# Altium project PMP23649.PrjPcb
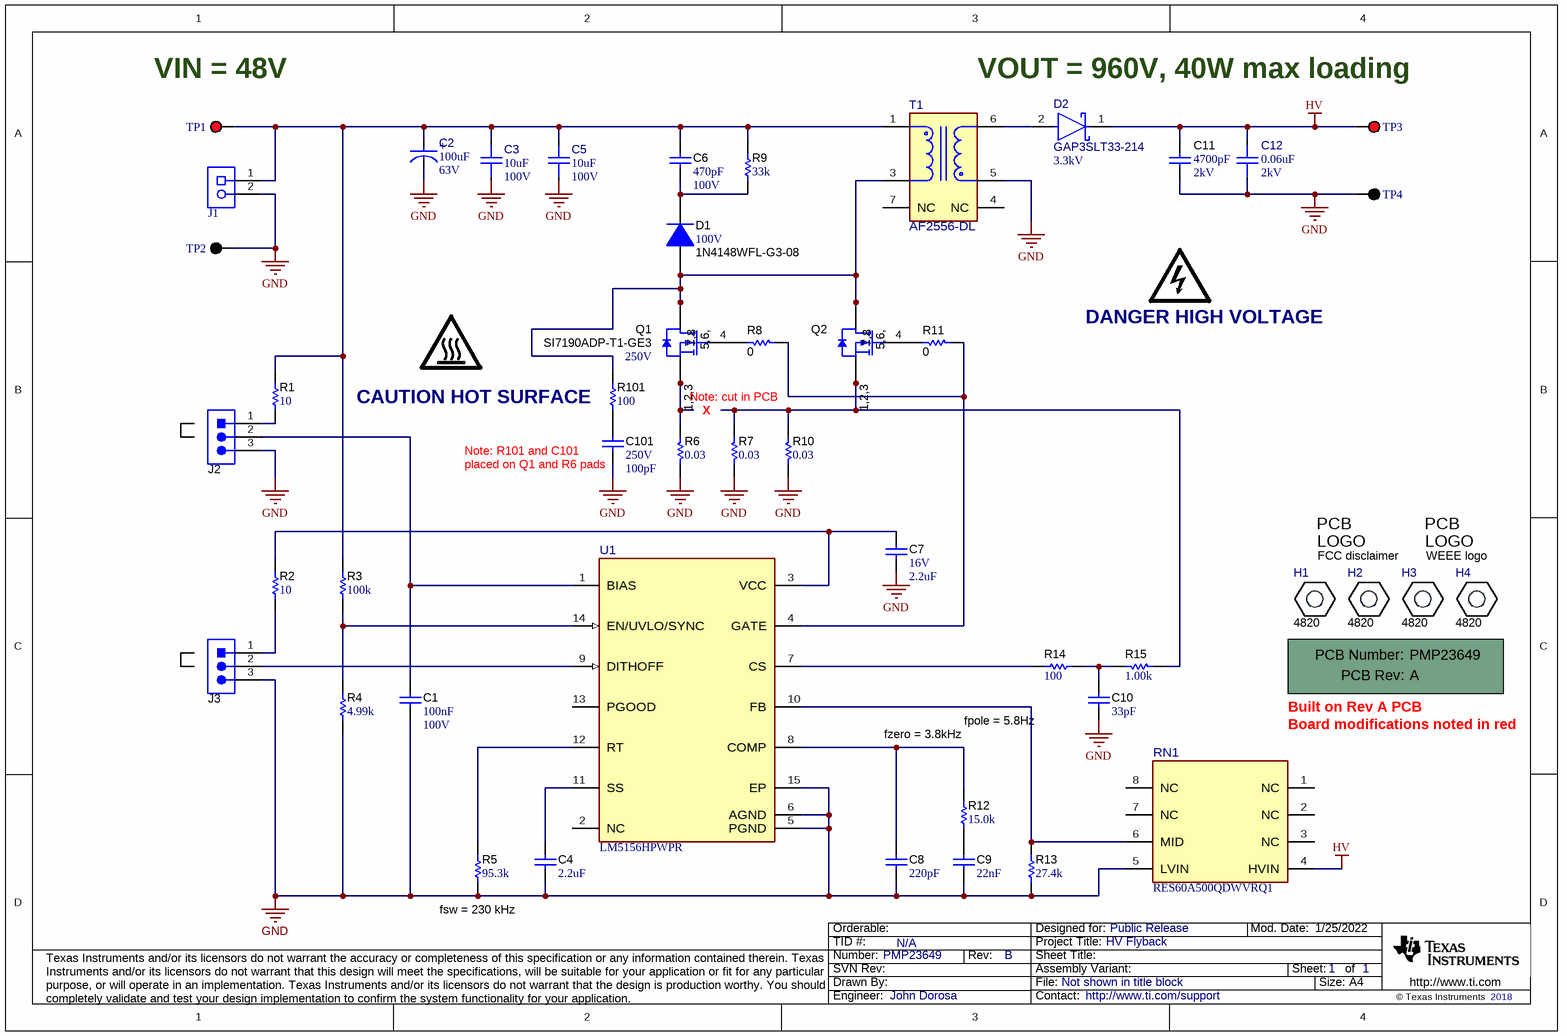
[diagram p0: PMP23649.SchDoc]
TID: N/A; TechSupport: http://www.ti.com/support; SCH_Rev: B; PRJ_Title: HV Flyback; PRJ_Number: PMP23649; PRJ_Engineer: John Dorosa; PRJ_Customer: Public Release; PCB_Rev: A; PCB_Layout: John Dorosa; CopyrightYear: 2018
1 sheet, 52 parts. Net scope: global (net labels, ports and power ports of the same name join across sheets).
Board file: PMP23649.PcbDoc

## Sheet PMP23649.SchDoc
size A4; Date: Not shown in title block; ApprovedBy: Not shown in title block; CheckedBy: Not shown in title block; Author: Not shown in title block; CompanyName: Not shown in title block; Engineer: Not shown in title block; Organization: Not shown in title block; Address1: Not shown in title block; Address2: Not shown in title block; Address3: Not shown in title block; Address4: Not shown in title block; DocumentNumber: 1; Revision: Use project parameter SCH_Rev; SheetNumber: 1; SheetTotal: 1; PageSetup: Record=PageOptions¦CenterHorizontal=True¦CenterVertical=True¦PrintScale=1.00¦XCorrection=1.00¦YCorrection=1.00¦PrintKind=0¦BorderSize=5000000¦LeftOffset=0¦BottomOffset=0¦Orientation=2¦PaperLength=1000¦PaperWidth=1000¦Scale=100¦PaperSource=15¦PrintQuality=600¦MediaType=1¦DitherType=10¦PaperKind=Letter¦PrintScaleMode=1

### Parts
!PCB1  Printed Circuit Board  (value not drawn)  (mechanical)
C1  Cap_F: 100nF  VDC_V: 100V  [0603]  (hidden comment: GRM188R72A104KA35D)
C2  ValueDisplayed: 100uF  VDC_V: 63V  [FP-HHXD630ARA101MJA0G_SMT_CAP_10MM3_10MM3-MFG]  (hidden comment: HHXD630ARA101MJA0G)
C3  ValueDisplayed: 10uF  VDC_V: 100V  [FP-GRM32EC72A106KE05L_1210-MFG]  (hidden comment: GRM32EC72A106KE05L)
C4  ValueDisplayed: 2.2uF  [0603]  (hidden comment: GRM188R61C225KAAD)
C5  ValueDisplayed: 10uF  VDC_V: 100V  [FP-GRM32EC72A106KE05L_1210-MFG]  (hidden comment: GRM32EC72A106KE05L)
C6  Cap_F: 470pF  VDC_V: 100V  [0603]  (hidden comment: 06031C471JAT2A)
C7  VDC_V: 16V  ValueDisplayed: 2.2uF  [0603]  (hidden comment: GRM188R61C225KAAD)
C8  Cap_F: 220pF  [0603]  (hidden comment: GRM188R71H221KA01D)
C9  Cap_F: 22nF  [0603]  (hidden comment: GRM188R71H223KA01D)
C10  ValueDisplayed: 33pF  [0603]  (hidden comment: GRM1885C1H330JA01D)
C11  VDC_V: 2kV  ValueDisplayed: 4700pF  [1210_230]  (hidden comment: C1210C472KGRACTU)
C12  ValueDisplayed: 0.06uF  VDC_V: 2kV  [FP-CKC33C603KGGLCAUTO_3640-MFG]  (hidden comment: CKC33C603KGGLCAUTO)
C101  VDC_V: 250V  ValueDisplayed: 100pF  [0805_HV]  (hidden comment: CL21C101JECNNWC)
D1  1N4148WFL-G3-08  value 100V  [SOD-123FL]
D2  GAP3SLT33-214  Vf_V: 3.3kV  [FP-GAP3SLT33-214_DO-214AA-MFG]
H1  4820  [KEYSTONE_4820]
H2  4820  [KEYSTONE_4820]
H3  4820  [KEYSTONE_4820]
H4  4820  [KEYSTONE_4820]
J1  ED120/2DS  [On-Shore_ED120_2DS]  (value not drawn)
J2  PEC03SAAN  [CONN_PEC03SAAN]  (value not drawn)
J3  PEC03SAAN  [CONN_PEC03SAAN]  (value not drawn)
LOGO1  CAUTION HOT SURFACE  [IEC_HotSurface_Small]  (no BOM)
LOGO2  DANGER HIGH VOLTAGE  [IEC_HighVoltage_Medium]  (no BOM)
Logo3  FCC disclaimer  [FCC_disclaimer]  (no BOM)
Logo4  WEEE logo  [WEEE_Minimum]  (no BOM)
Q1  SI7190ADP-T1-GE3  value 250V  [PowerPAK_SO-8]
Q2  SI7190ADP-T1-GE3  [PowerPAK_SO-8]  (value not drawn)
R1  ValueDisplayed: 10  [0603]  (hidden comment: CRCW060310R0JNEA)
R2  ValueDisplayed: 10  [0603]  (hidden comment: CRCW060310R0JNEA)
R3  ValueDisplayed: 100k  [0603]  (hidden comment: CRCW0603100KFKEA)
R4  ValueDisplayed: 4.99k  [0603]  (hidden comment: CRCW06034K99FKEAC)
R5  ValueDisplayed: 95.3k  [0603]  (hidden comment: CRCW060395K3FKEA)
R6  ValueDisplayed: 0.03  [WSLP0805]  (hidden comment: WSLP0805R0300FEB)
R7  ValueDisplayed: 0.03  [WSLP0805]  (hidden comment: WSLP0805R0300FEB)
R8  ValueDisplayed: 0  [0603]  (hidden comment: CRCW06030000Z0EA)
R9  ValueDisplayed: 33k  [1210]  (hidden comment: RC1210JR-0733KL)
R10  ValueDisplayed: 0.03  [WSLP0805]  (hidden comment: WSLP0805R0300FEB)
R11  ValueDisplayed: 0  [0603]  (hidden comment: CRCW06030000Z0EA)
R12  ValueDisplayed: 15.0k  [0603]  (hidden comment: CRCW060315K0FKEA)
R13  ValueDisplayed: 27.4k  [0603]  (hidden comment: CRCW060327K4FKEA)
R14  ValueDisplayed: 100  [0603]  (hidden comment: CRCW0603100RFKEA)
R15  ValueDisplayed: 1.00k  [0603]  (hidden comment: CRCW06031K00FKEA)
R101  ValueDisplayed: 100  [1210]  (hidden comment: RC1210JR-07100RL)
RN1  RES60A500QDWVRQ1  [DWV0008A-MFG]
T1  AF2556-DL  [FP-AF2556-DL_PTH_XFRMR_33MM5_26MM0-MFG]
TP1  5010  [Keystone5010]  (value not drawn)
TP2  5011  [Keystone5011]  (value not drawn)
TP3  5010  [Keystone5010]  (value not drawn)
TP4  5011  [Keystone5011]  (value not drawn)
U1  LM5156HPWPR  [PWP0014H-MFG]

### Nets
GND: C1.2 C2.1(CATHODE) C3.1 C4.2 C5.1 C7.2 C8.2 C9.2 C10.1 C11.2 C12.1 C101.2 J1.2 J2.3 J3.3 R4.1 R5.1 R6.1 R7.1 R10.1 R13.1 RN1.5(LVIN) T1.5 TP2.1 TP4.1 U1.5(PGND) U1.6(AGND) U1.15(EP)
HV: C11.1 C12.2 D2.1(K) RN1.4(HVIN) TP3.1
NetC1_1: C1.1 J2.2 U1.1(BIAS)
NetC2_2: C2.2(ANODE) C3.2 C5.2 C6.1 J1.1 R1.1 R3.2 R9.2 T1.1 TP1.1
NetC4_1: C4.1 U1.11(SS)
NetC6_2: C6.2 D1.1(K) R9.1
NetC7_1: C7.1 R2.2 U1.3(VCC)
NetC8_1: C8.1 R12.2 U1.8(COMP)
NetC9_1: C9.1 R12.1
NetC10_2: C10.2 R14.2 R15.2
NetC101_1: C101.1 R101.1
NetD1_2: D1.2(A) Q1.5(D) Q1.6(D) Q1.7(D) Q1.8(D) Q1.9(D) Q2.5(D) Q2.6(D) Q2.7(D) Q2.8(D) Q2.9(D) R101.2 T1.3
NetD2_2: D2.2(A) T1.6
NetJ2_1: J2.1 R1.2
NetJ3_1: J3.1 R2.1
NetJ3_2: J3.2 U1.9(DITHOFF)
NetQ1_1: Q1.1(S) Q1.2(S) Q1.3(S) R6.2
NetQ1_4: Q1.4(G) R8.1
NetQ2_1: Q2.1(S) Q2.2(S) Q2.3(S) R7.2 R10.2 R15.1
NetQ2_4: Q2.4(G) R11.1
NetR3_1: R3.1 R4.2 U1.14(EN/UVLO/SYNC)
NetR5_2: R5.2 U1.12(RT)
NetR8_2: R8.2 R11.2 U1.4(GATE)
NetR13_2: R13.2 RN1.6(MID) U1.10(FB)
NetR14_1: R14.1 U1.7(CS)

Not connected (* = marked no-connect by the designer): RN1 1(NC) 2(NC) 3(NC) 7(NC) 8(NC); T1 4(NC) 7(NC); U1 2(NC) 13(PGOOD)

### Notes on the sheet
- (near TP1) VIN = 48V
- VOUT = 960V, 40W max loading
- Note: R101 and C101
- X
- Note: cut in PCB
- (near C101) placed on Q1 and R6 pads
- fpole = 5.8Hz
- (near !PCB1) Built on Rev A PCB
- fzero = 3.8kHz
- Board modifications noted in red
- (near R5) fsw = 230 kHz

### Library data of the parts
!PCB1 = CMP-0003618-2: Manufacturer: Any; PartNumber: PMP23649
C1 = CMP-0007469-4: CAP, CERM, 0.1 uF, 100 V, +/- 10%, X7R, 0603; Manufacturer: MuRata; TaMin_C: -55°C; Polarized: N; SizeAreaWB_mm2: 4.68; Value1: Unknown; U/M: EA; Value: 0.1uF; TaMax_C: 125°C; SizeZ_mm: 1; SizeX_mm: 1.6; SizeY_mm: 0.8; SizeArea_mm2: 1.28; AEC Category: Q200
C2 = CMP-0122594-1: 100 µF 63 V Aluminum - Polymer Capacitors Radial, Can - SMD 30mOhm 10000 Hrs @ 105°C; Manufacturer: Chemi-Con; AEC Grade: Grade 2; AEC Qualified: Yes; Cap_F: 100µF; IRMS_A: 2.4A; SizeZ_mm: 10.3mm; Tolerance_%: 20%; Dissipation Factor: 8%; Esr: 30m; Leakage Current: 63uA; Life: 10000Hours; Value: 100µF
C3 C5 = CMP-0087970-1: 10µF ±10% 100V Ceramic Capacitor X7S 1210 (3225 Metric); Manufacturer: Murata; Symbol Name: SYM-GRM32EC72A106KE05L; AEC Qualified: No; TempCo: 22%; SizeZ_mm: 2.7mm
C4 = CMP-0007338-5: CAP, CERM, 2.2 uF, 16 V, +/- 10%, X5R, 0603; Manufacturer: MuRata; TaMin_C: -55°C; Polarized: N; SizeAreaWB_mm2: 4.68; Value1: Unknown; U/M: EA; Value: 2.2uF; TaMax_C: 85°C; SizeZ_mm: 1; SizeX_mm: 1.6; SizeY_mm: 0.8; Value2: 16V; SizeArea_mm2: 1.28; Cap_F: 2.2µF; AEC Category: Q200
C6 = CMP-0006743-4: CAP, CERM, 470 pF, 100 V, +/- 5%, X7R, 0603; Manufacturer: AVX; TaMin_C: -55°C; ESR_ohm: 0.397; Polarized: N; SizeAreaWB_mm2: 4.68; Value1: 0.397 ohm; U/M: EA; Value: 470pF; TaMax_C: 125°C; SizeZ_mm: 1; SizeX_mm: 1.6; SizeY_mm: 0.8; SizeArea_mm2: 1.28; AEC Category: Q200
C7 = CMP-0007338-5: CAP, CERM, 2.2 uF, 16 V, +/- 10%, X5R, 0603; Manufacturer: MuRata; TaMin_C: -55°C; Polarized: N; SizeAreaWB_mm2: 4.68; Value1: Unknown; U/M: EA; Value: 2.2uF; TaMax_C: 85°C; SizeZ_mm: 1; SizeX_mm: 1.6; SizeY_mm: 0.8; SizeArea_mm2: 1.28; Cap_F: 2.2µF; AEC Category: Q200
C8 = CMP-0007442-5: CAP, CERM, 220 pF, 50 V, +/- 10%, X7R, 0603; Manufacturer: MuRata; TaMin_C: -55°C; Polarized: N; SizeAreaWB_mm2: 4.68; Value1: Unknown; U/M: EA; Value: 220pF; TaMax_C: 125°C; SizeZ_mm: 1; SizeX_mm: 1.6; SizeY_mm: 0.8; Value2: 50V; SizeArea_mm2: 1.28; AEC Category: Q200
C9 = CMP-0007444-5: CAP, CERM, 0.022 uF, 50 V, +/- 10%, X7R, 0603; Manufacturer: MuRata; U/M: EA; SizeX_mm: 1.6; Polarized: N; TaMin_C: -55°C; SizeZ_mm: 1; AEC Category: Q200; SizeAreaWB_mm2: 4.68; SizeY_mm: 0.8; Value2: 50V; TaMax_C: 125°C; SizeArea_mm2: 1.28; MFG_Status: TI_Obsolete; Value1: Unknown
C10 = CMP-0007208-4: CAP, CERM, 33 pF, 50 V, +/- 5%, C0G/NP0, 0603; Manufacturer: MuRata; TaMin_C: -55°C; Polarized: N; SizeAreaWB_mm2: 4.68; Value1: Unknown; U/M: EA; Value: 33pF; TaMax_C: 125°C; SizeZ_mm: 1; SizeX_mm: 1.6; SizeY_mm: 0.8; Value2: 50V; SizeArea_mm2: 1.28; AEC Category: Q200
C11 = CMP-0009087-1: CAP, CERM, 4700 pF, 2000 V, +/- 10%, X7R, 1210; Manufacturer: Kemet; TaMin_C: -55°C; Polarized: N; SizeAreaWB_mm2: 14.7; Value1: Unknown; U/M: EA; Value: 4700pF; TaMax_C: 125°C; SizeZ_mm: 2.3; SizeX_mm: 3.2; SizeY_mm: 2.5; Cap_Case: 1210; Value2: 2000V; SizeArea_mm2: 8; Cap_F: 4.7nF; AEC Category: Q200
C12 = CMP-0124311-1: 0.06 µF ±10% 2000V (2kV) Ceramic Capacitor C0G, NP0 3640 (9110 Metric); Manufacturer: KEMET; AEC Grade: Grade 0; AEC Qualified: Yes; Cap_F: 60nF; SizeZ_mm: 11.1mm; TempCo: 30ppm/°C; Value: 60nF
C101 = CMP-0074690-1: CAP, CERM, 100 pF, 250 V,+/- 5%, C0G/NP0, 0805; Manufacturer: Samsung Electro-Mechanics; TaMin_C: -55°C; Polarized: N; SizeAreaWB_mm2: 6.75; U/M: EA; Value: 100pF; TaMax_C: 125°C; SizeZ_mm: 1.45; SizeX_mm: 2.0; SizeY_mm: 1.25; Cap_Case: 0805; SizeArea_mm2: 2.5; AEC Category: Q200
D1 = CMP-0076920-3: Diode, Switching, 100 V, 0.15 A, SOD-123FL; Manufacturer: Vishay-Semiconductor; TJmax_C: 150°C; SizeX_mm: 3.6; SizeArea_mm2: 5.94; AEC Category: Q101; SizeY_mm: 1.65; Value1: 0.15A; Io_A: 150mA; SizeZ_mm: 0.98; SizeAreaWB_mm2: 12.19; Green_Lifecycle: Not Set; MFG_Status: TI_Obsolete; Value2: 1.2V; Green_REACh: Incomplete
D2 = CMP-0124313-1: Rectifier Diode Schottky SiC 3.3KV 0.3A 2-Pin SMB; Manufacturer: GeneSiC Semiconductor; AEC Qualified: No; SizeZ_mm: 2.44mm; TJmax_C: 175°C; Cap_F: 93pF; Max Surge Forward Current: 2A; Peak Reverse Current: 1uA
H1-H4 = CMP-0003652-1: Manufacturer: Keystone; CompType: Standoff
J1 = CMP-0074910-1: Terminal Block, 5.08 mm, 2x1, Brass, TH; Manufacturer: On-Shore Technology; Cert_VDE: Y; CNHeader: False; Current_A: 15A; Green_Lifecycle: Not Set; Shrouded: N; Gender: Female; Green_REACh: Incomplete; Voltage_V: 300V; Row_Count: 1; Pitch_mm: 5.08; CT: True
J2 J3 = CMP-0002338-1: Header, 100mil, 3x1, Tin, TH; Manufacturer: Sullins Connector Solutions; CNHeader: TRUE; Current_A: 3A; Green_Lifecycle: Not Set; Shrouded: N; Gender: Male; Green_REACh: Incomplete; Voltage_V: 1.8kV; Row_Count: 1; Pitch_mm: 2.54; CT: FALSE; Cert_UL: Y
LOGO1 = CMP-0074837-1: IEC 61010-1 Hot Surface Warning; SymbolCreator: a0412235
LOGO2 = CMP-0074835-1: IEC 61010-1 High Voltage Warning; SymbolCreator: a0412235
Logo3 = CMP-0074847-1: FCC_disclaimer; Library Reference: Logo
Logo4 = CMP-0074769-1
Q1 = CMP-0084047-1: MOSFET, N-CH, 250 V, 18.4 A, PowerPAK SO-8; Manufacturer: Vishay-Semiconductor; Alternate Manufacturer: None; ChType: N; QgTyp_nC: 32; SizeAreaWB_mm2: 55.131; SizeArea_mm2: 29.351; IdsMax_A: 18.4A; Vgs_V: 20V; AEC Category: Q101; SizeZ_mm: 1.12; ChMode: Enhancement; SizeY_mm: 4.9; Value2: 32 nC; Value1: ? ohm; SizeX_mm: 5.99
Q2 = CMP-0084047-1: MOSFET, N-CH, 250 V, 18.4 A, PowerPAK SO-8; Manufacturer: Vishay-Semiconductor; Alternate Manufacturer: None; ChType: N; QgTyp_nC: 32; SizeAreaWB_mm2: 55.131; SizeArea_mm2: 29.351; IdsMax_A: 18.4A; VdsMax_V: 250V; Vgs_V: 20V; AEC Category: Q101; Value: 250V; SizeZ_mm: 1.12; ChMode: Enhancement; SizeY_mm: 4.9; Value2: 32 nC; Value1: ? ohm; SizeX_mm: 5.99
R1 R2 = CMP-0025703-4: RES, 10, 5%, 0.1 W, AEC-Q200 Grade 0, 0603; Manufacturer: Vishay-Dale; Power_W: 100mW; TempCo: 200 ppm/C; Value_Code: 10R0; Value: 10; EIA_Code: E24; SizeX_mm: 1.6; SizeY_mm: 0.8; SizeZ_mm: 1; Value2: 0.1W; SizeArea_mm2: 1.28; AEC Qualified: Y; VDC_V: 75V; AEC Category: Q200; AEC Grade: 0
R3 = CMP-0021990-4: RES, 100 k, 1%, 0.1 W, AEC-Q200 Grade 0, 0603; Manufacturer: Vishay-Dale; Power_W: 100mW; TempCo: 100 ppm/C; Value: 100k; EIA_Code: E96; SizeX_mm: 1.6; SizeY_mm: 0.8; SizeZ_mm: 1; Value2: 0.1W; SizeArea_mm2: 1.28; AEC Qualified: Y; VDC_V: 75V; AEC Category: Q200; AEC Grade: 0
R4 = CMP-0082533-1: RES, 4.99 k, 1%, 0.1 W, 0603; Manufacturer: Vishay-Dale; Power_W: 100mW; TempCo: 100 ppm/C; SizeAreaWB_mm2: 4.68; Value_Code: 4k99; Value: 4.99k; EIA_Code: E96; SizeX_mm: 1.6; SizeY_mm: 0.8; SizeZ_mm: 1; Value2: 0.1W; SizeArea_mm2: 1.28; AEC Qualified: N; VDC_V: 75V; AEC Category: Q200
R5 = CMP-0022659-4: RES, 95.3 k, 1%, 0.1 W, AEC-Q200 Grade 0, 0603; Manufacturer: Vishay-Dale; Power_W: 100mW; TempCo: 100 ppm/C; Value_Code: 95k3; Value: 95.3k; EIA_Code: E96; SizeX_mm: 1.6; SizeY_mm: 0.8; SizeZ_mm: 1; Value2: 0.1W; SizeArea_mm2: 1.28; AEC Qualified: Y; VDC_V: 75V; AEC Category: Q200; AEC Grade: 0
R6 R7 R10 = CMP-0021987-2: RES, 0.03, 1%, 0.5 W, 0805; Manufacturer: Vishay-Dale; Power_W: 500mW; TempCo: 75 ppm/C; Value_Code: R030; U/M: EA; Value: 0.03; EIA_Code: E96; Res_ohm: 30m; SizeX_mm: 2.03; SizeY_mm: 1.27; SizeZ_mm: 0.635; Value2: 0.5W; SizeArea_mm2: 2.5781; AEC Qualified: N; AEC Category: Q200
R8 R11 = CMP-0025697-4: RES, 0, 5%, 0.1 W, AEC-Q200 Grade 0, 0603; Manufacturer: Vishay-Dale; Power_W: 100mW; TempCo: 200 ppm/C; Value_Code: 0000; Value: 0; EIA_Code: E24; SizeX_mm: 1.6; SizeY_mm: 0.8; SizeZ_mm: 1; Value2: 0.1W; SizeArea_mm2: 1.28; AEC Qualified: Y; VDC_V: 75V; AEC Category: Q200
R9 = CMP-0083530-1: RES, 33 k, 5%, 0.5 W, 1210; Manufacturer: Yageo; Power_W: 500mW; TempCo: 100 ppm/C; SizeAreaWB_mm2: 14.7; Value_Code: 33k0; Value: 33k; EIA_Code: E24; SizeX_mm: 3.2; SizeY_mm: 2.5; SizeZ_mm: 1.35; Value2: 0.5W; SizeArea_mm2: 8; AEC Qualified: N; VDC_V: 200V; AEC Category: Q200
R12 = CMP-0022066-4: RES, 15.0 k, 1%, 0.1 W, AEC-Q200 Grade 0, 0603; Manufacturer: Vishay-Dale; Power_W: 100mW; TempCo: 100 ppm/C; Value_Code: 15k0; Value: 15.0k; EIA_Code: E96; Res_ohm: 15k; SizeX_mm: 1.6; SizeY_mm: 0.8; SizeZ_mm: 1; Value2: 0.1W; SizeArea_mm2: 1.28; AEC Qualified: Y; VDC_V: 75V; AEC Category: Q200; AEC Grade: 0
R13 = CMP-0022254-4: RES, 27.4 k, 1%, 0.1 W, AEC-Q200 Grade 0, 0603; Manufacturer: Vishay-Dale; Power_W: 100mW; TempCo: 100 ppm/C; Value_Code: 27k4; Value: 27.4k; EIA_Code: E96; SizeX_mm: 1.6; SizeY_mm: 0.8; SizeZ_mm: 1; Value2: 0.1W; SizeArea_mm2: 1.28; AEC Qualified: Y; VDC_V: 75V; AEC Category: Q200; AEC Grade: 0
R14 = CMP-0021991-4: RES, 100, 1%, 0.1 W, AEC-Q200 Grade 0, 0603; Manufacturer: Vishay-Dale; Power_W: 100mW; TempCo: 100 ppm/C; Value_Code: 100R; Value: 100; EIA_Code: E96; SizeX_mm: 1.6; SizeY_mm: 0.8; SizeZ_mm: 1; Value2: 0.1W; SizeArea_mm2: 1.28; AEC Qualified: Y; VDC_V: 75V; AEC Category: Q200; AEC Grade: 0
R15 = CMP-0022109-5: RES, 1.00 k, 1%, 0.1 W, AEC-Q200 Grade 0, 0603; Manufacturer: Vishay-Dale; Power_W: 100mW; TempCo: 100 ppm/C; Value_Code: 1k00; Value: 1.00k; EIA_Code: E96; Res_ohm: 1k; SizeX_mm: 1.6; SizeY_mm: 0.8; SizeZ_mm: 1; Value2: 0.1W; SizeArea_mm2: 1.28; AEC Qualified: Y; VDC_V: 75V; AEC Category: Q200; AEC Grade: 0
R101 = CMP-0083441-1: RES, 100, 5%, 0.5 W, 1210; Manufacturer: Yageo; Power_W: 500mW; TempCo: 100 ppm/C; SizeAreaWB_mm2: 14.7; Value_Code: 100R; Value: 100; EIA_Code: E24; SizeX_mm: 3.2; SizeY_mm: 2.5; SizeZ_mm: 1.35; Value2: 0.5W; SizeArea_mm2: 8; AEC Qualified: N; VDC_V: 200V; AEC Category: Q200
RN1 = CMP-0122658-1: Automotive, 1700-V, Precision Resistive Divider; Manufacturer: Texas Instruments; SizeZ_mm: 2.8mm; AEC Qualified: Yes; AEC Grade: Grade 1; Number Of Resistors: 2; Standoff Height: 0.36mm; TaMax_C: +125°C; TaMin_C: -40°C; TempCo: 1ppm/°C; TJmax_C: +150°C; Tolerance_%: 0.05%; VDC_V: 1700V
T1 = CMP-0124541-1: Flyback Transformer; Manufacturer: Coilcraft; DCR_ohm: 0.11; Ind_H: 25µH; Ns1toNp: 1:10; Rsec1_ohm: 4.07; SizeZ_mm: 12mm; Voltage_Isolation_Vrms: 3.5kV
TP1 TP3 = CMP-0055147-2: Test Point, Multipurpose, Red, TH; Manufacturer: Keystone Electronics; CT: TRUE; ContactFinish: Silver; Green_Lifecycle: Active; CNHeader: FALSE; Green_REACh: Passed
TP2 TP4 = CMP-0055148-2: Test Point, Multipurpose, Black, TH; Manufacturer: Keystone Electronics; CNHeader: FALSE; ContactFinish: Silver; Green_REACh: Passed; Green_Lifecycle: Active; CT: TRUE
U1 = CMP-0090862-1: 2.2-MHz Wide VIN 65-V Non-synchronous Boost/SEPIC/Flyback Controller with 150°C Junction Temperature; Manufacturer: Texas Instruments; Number Of Outputs: 1; Standoff Height: 0.05mm; Max Duty Cycle: 96%; Max Supply Voltage: 60V; TaMax_C: +125°C; AEC Qualified: Yes; Output Type: AdjustableProgrammable; AEC Grade: Grade 1; Nominal Supply Current: 490uA; TJmax_C: +150°C; TaMin_C: -40°C; Switching Frequency: 100-2200kHz; Switching Topology: Boost,Flyback,Other; Min Supply Voltage: 2.97V; SizeZ_mm: 1.2mm

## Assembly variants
001: not fitted H1 H2 H3 H4 Q1 R6 R8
